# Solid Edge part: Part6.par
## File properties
Author: Vicky Raina
Template: Normal.par
Last saved by: Robert a Rhodes jr
Revision: 2
Application: Solid Edge
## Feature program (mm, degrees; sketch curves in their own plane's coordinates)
body "unnamed Body 1"
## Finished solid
Body 1: solid body, 43 faces, 102 edges, 68 vertices.
  Faces by surface: cylinder 28, plane 15
  Edges by curve: circle 56, line 46
Bounding box of the edges (mm): 1353.852 x 457.200 x 1295.400, from (-676.9261, -203.2, -533.4) to (676.9261, 254, 762).
Cylindrical faces by radius (mm): R50.8 x6, R95.25 x6, R127 x5, R152.4 x2, R254 x2, R431.8 x2, R508 x2, R533.4 x3
Planar faces by outward normal: +x 1, +y 7, -x 1, -y 2, oblique 4
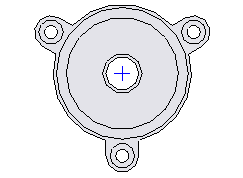
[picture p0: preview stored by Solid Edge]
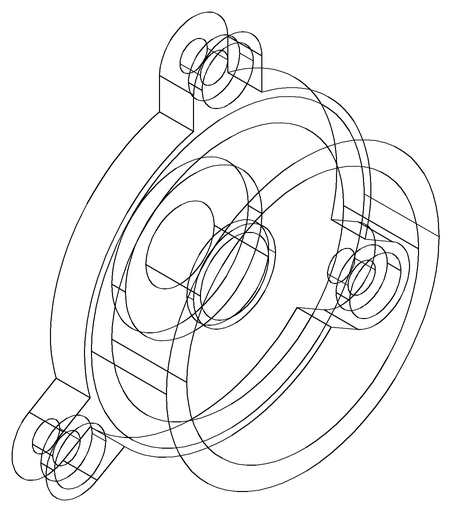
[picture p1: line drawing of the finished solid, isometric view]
